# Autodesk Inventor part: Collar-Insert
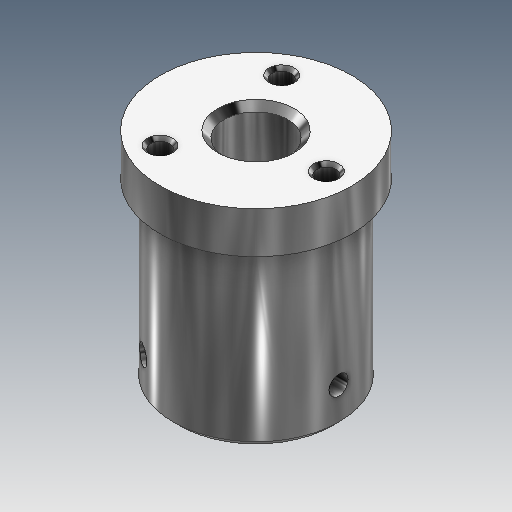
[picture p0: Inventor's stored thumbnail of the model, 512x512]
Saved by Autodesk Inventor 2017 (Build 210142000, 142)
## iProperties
Shininess: 64.0
Length Units: 11269
Angle Units: 11279
Time Units: 11290
Mass Units: 11283
Length Display Precision: 3
Angle Display Precision: 2
Compacted: True
Part Number: Collar-Insert
Document SubType Name: Modeling
Created: 2004-01
Designer: Administrator
Manufacturer: Standard
Standards Organization: Custom
Density: 1 g/cm^3
Material: Generic
Appearance: Chrome - Polished
Density: 0.0
Volumn: 0.0
Area: 0.0
PropertySet Name: Model Information
Control State: 0
Master: False
Checked Out: False
Author: Administrator
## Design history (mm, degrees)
sketch "Sketch1"
  geometry: L1 (15, 34.5)-(15, 31) reference; L2 (13, 31)-(13, 3.5) reference; L3 (15, 31)-(13, 31); L4 (5, 37.5)-(5, 3.5); L5 (13, 3.5)-(5, 3.5); L6 (5, 37.5)-(15, 37.5); L7 (15, 37.5)-(15, 34.5); L8 (0, -3.3)-(0, 44.3) reference
  constraints: 10 end point, 3 perpendicular, 2 parallel
  dimensions: "d0" = 8 distance between parallel lines of L4 L2; "d1" = 34 distance of L4.start L4.end
revolve "Revolution1" sketch "Sketch1" stored, may be unused: angle "d2" = 90 deg
chamfer "Chamfer1" distance "d5" = 1; stored, may be unused: second distance "d6" = 2, angle "d7" = 45 deg
chamfer "Chamfer2" distance "d8" = 1; stored, may be unused: second distance "d9" = 2, angle "d10" = 45 deg
workplane "Work Plane1"
sketch "Sketch3"
  geometry: 1 further point
hole "Hole1" sketch "Sketch3" at (-7.75, 0) diameter "d11" = 3; stored, may be unused: countersink angle "d15" = 82 deg, drill point angle "d17" = 118 deg; dims "d12" = 6, "d13" = 4, "d14" = 2, "d16" = 5
pattern_circular "Circular Pattern1" dims angle "d20" = 360 deg
sketch "Sketch4" dims "d21" = 22
  geometry: L1 (0, 0)-(13.088, 0); C1 r 6 at (0, 0) reference; 1 further point
  constraints: 2 end point, 1 coincident, 1 horizontal, 1 horizontal alignment, 1 point on line, 2 other
hole "Hole2" sketch "Sketch4" at (11, 0) diameter "d22" = 3; stored, may be unused: countersink angle "d26" = 82 deg, drill point angle "d28" = 118 deg; dims "d23" = 6, "d24" = 4, "d25" = 2, "d27" = 8
pattern_circular "Circular Pattern2" dims angle "d31" = 360 deg
chamfer "Chamfer3" distance "d32" = 0.5; stored, may be unused: second distance "d33" = 2, angle "d34" = 45 deg
body "Solid1"
